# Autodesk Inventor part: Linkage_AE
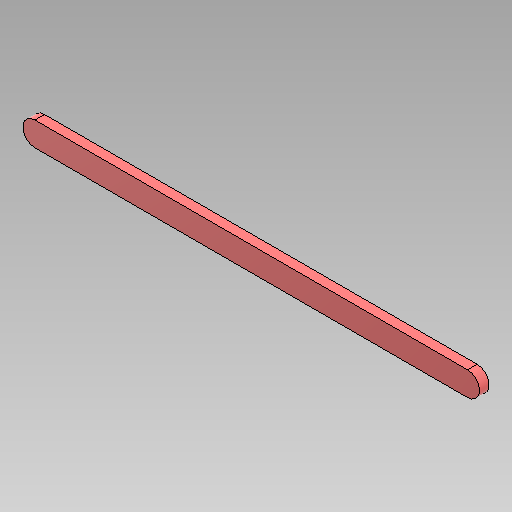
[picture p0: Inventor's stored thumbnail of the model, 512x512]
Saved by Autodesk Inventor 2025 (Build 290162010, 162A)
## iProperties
Created: 2024-10
Part Number: Linkage_AE
Material: Generic
Document SubType Name: Modeling
Designer: Dennis
Density: 1 g/cm^3
Appearance: Smooth - Red
Mass: 0.93927 g
Surface Area: 13.3069 cm^2
Volume: 0.93927 cm^3
Author: Dennis
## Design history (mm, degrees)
sketch "Sketch1"
  geometry: L1 (0, 0)-(90, 0); L2 (0, -2.5)-(90, -2.5); L3 (90, 2.5)-(0, 2.5); A1 r 2.5 centre (0, 0) between (0, 2.5) and (0, -2.5); A2 r 2.5 centre (90, 0) between (90, -2.5) and (90, 2.5); 1 further point
  constraints: 8 end point, 4 point on circle, 4 tangent, 2 centre point, 1 horizontal, 1 midpoint, 1 parallel
  dimensions: "d0" = 5 distance between parallel lines of L2 L3 (= w_); "d1" = 90 distance of L1.start L1.end (= AE_)
extrude "Extrusion1" new body sketch "Sketch1" stored distance "d2" = 2 (= t_); taper "d3" = 0 deg
body "Solid1"
other parameters: "AE_" = 90 [user parameter; used in 1 equation term], "w_" = 5 [user parameter; used in 1 equation term], "t_" = 2 [user parameter; used in 1 equation term]
